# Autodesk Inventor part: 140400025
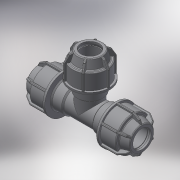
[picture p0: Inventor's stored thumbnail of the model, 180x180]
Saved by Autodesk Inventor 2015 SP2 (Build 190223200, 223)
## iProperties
Created: 2017-08
Part Number: 140400025
Material: Generic
Description: PLASSON L.14 TEE (SILVER) 25-25-25
Document SubType Name: Modeling
Designer: KIM
Density: 1 g/cm^3
Appearance: Default
Author: KIM
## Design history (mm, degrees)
derived "140400.ipt"
feature "Solid1::140400.ipt"
tag "TaggingFeature1"
body "Solid1"
other parameters: "d1" = 25, "d2" = 47, "d4" = 15 deg, "d5" = 31.02, "d6" = 10.2366, "d16" = 25.5, "d17" = 2.35, "d22" = 35, "d24" = 2.35, "d25" = 45, "d26" = 37.5, "d27" = 2.35, "d28" = 135 deg, "d29" = 1.41, "d31" = 1.25, "d46" = 150 deg, "d49" = 2.5, "d50" = 0, "d58" = 0.75, "d61" = 360 deg, "d63" = 22.5, "d64" = 62, "d78" = 180 deg, "d80" = 31.5, "d81" = 1.75, "d84" = 4.7, "d86" = 0, "d88" = 0, "d90" = 0, "d92" = 180 deg, "d_" = 25, "G_" = 18.631, "H_" = 124, "l_" = 47, "l_2" = 19
